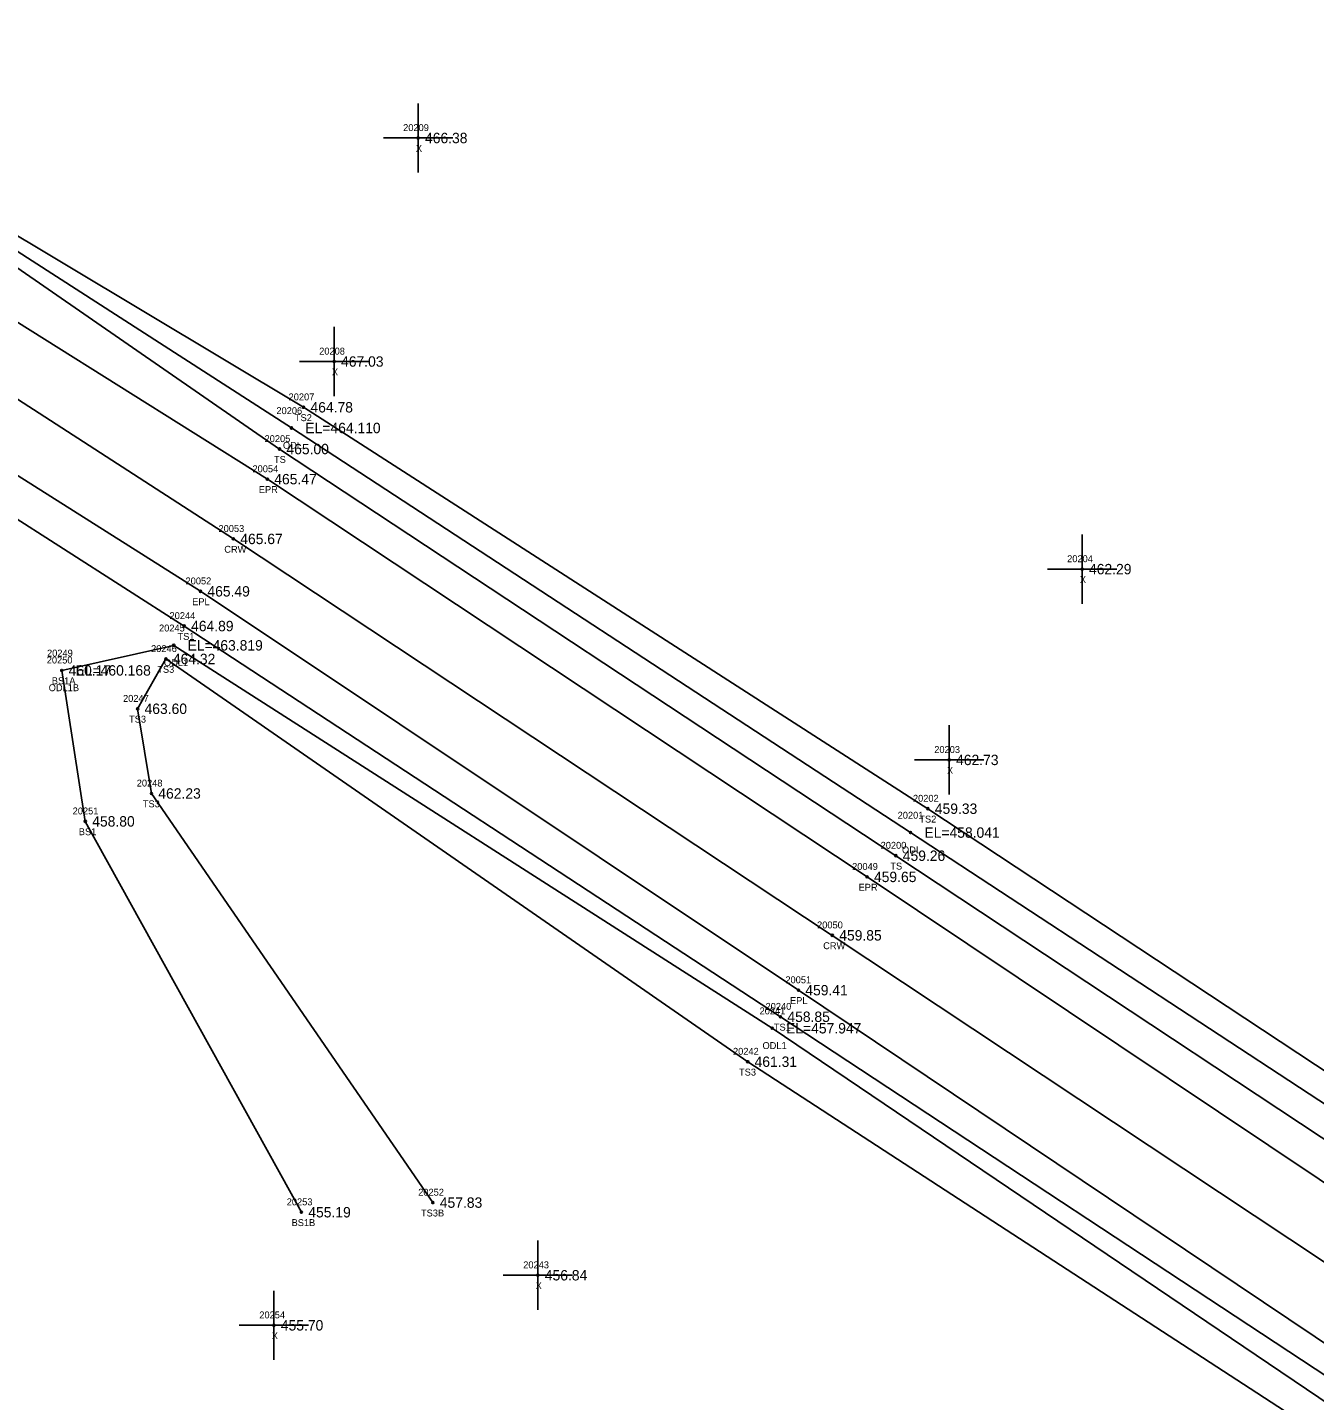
# Model space of a CAD drawing. Extents: x 1797709 to 1799052, y 896018 to 896955.
# Drawn here: x 1797809.4 to 1797995.4, y 896720 to 896918.3 of the extents above; entities that cross this region are included whole.
import ezdxf

# ---------------------------------------------------------------- set-up
doc = ezdxf.new("R2010")
doc.units = 0
for name, color, linetype in [('RD_DTM_BkLn1', 7, 'Continuous'), ('RD_DTM_BkLn2', 7, 'Continuous'), ('RD_DTM_BkLn_txCode', 7, 'Continuous'), ('RD_EX_H2O', 7, 'Continuous'), ('RD_EX_H2O_txCode', 7, 'Continuous'), ('RD_EX_Misc', 7, 'Continuous'), ('RD_EX_Misc_txCode', 7, 'Continuous'), ('RD_EX_Road', 7, 'Continuous'), ('RD_EX_Road_txCode', 7, 'Continuous'), ('RD_EX_TX_H2O_ELEV', 7, 'Continuous'), ('RD_EX_TX_Misc_ELEV', 7, 'Continuous'), ('RD_EX_TX_Road_ELEV', 7, 'Continuous'), ('RD_HC_Survey_ELEV', 7, 'Continuous'), ('RD_HC_Survey_txCode', 7, 'Continuous'), ('RD_SMD_Locator', 7, 'Continuous')]:
    doc.layers.add(name, color=color, linetype=linetype)

msp = doc.modelspace()

# ---------------------------------------------------------------- linework, layer by layer
at = {"layer": 'RD_DTM_BkLn1'}
msp.add_lwpolyline([(1798362.28, 896497.65), (1798275.53, 896555.51), (1798188.06, 896613.78), (1798100.6, 896671.09), (1798012.14, 896729.83), (1797925.7, 896787.19), (1797839.16, 896844.44), (1797754.21, 896899.34)], dxfattribs=at)
at = {"layer": 'RD_DTM_BkLn2'}
for points in [[(1798369.83, 896508.31), (1798367.91, 896513.92), (1798355.6, 896518.28), (1798283.49, 896566.57), (1798194.13, 896625.72), (1798108.66, 896683.13), (1798020.94, 896741.77), (1797934.88, 896798.69), (1797845.83, 896857.42), (1797757.7, 896918.3)], [(1798314.49, 896563.64), (1798288.01, 896573.8), (1798198.07, 896632.21), (1798113.28, 896689.71), (1798026.02, 896748.38), (1797939.51, 896805.48), (1797849.3, 896863.45), (1797757.7, 896918.3)], [(1798355.54, 896486.7), (1798350.74, 896485.38), (1798342.98, 896495.49), (1798267.09, 896545.1), (1798179.21, 896602.99), (1798092.54, 896661.13), (1798003.24, 896719.48), (1797918.21, 896775.43), (1797832.05, 896831.86), (1797744.82, 896887.66)], [(1798197.99, 896581.94), (1798175.06, 896597.9), (1798088.07, 896654.61), (1797998.87, 896713.42), (1797913.47, 896768.94), (1797829.42, 896827.1), (1797825.33, 896819.91), (1797827.32, 896807.68), (1797867.99, 896748.59)], [(1797814.36, 896825.45), (1797817.77, 896803.65), (1797848.99, 896747.2)]]:
    msp.add_lwpolyline(points, dxfattribs=at)
at = {"layer": 'RD_EX_H2O'}
for points in [[(1798314.49, 896563.64), (1798286.18, 896571.49), (1798196.7, 896629.98), (1798111.06, 896686.41), (1798023.38, 896745.41), (1797937.01, 896802.03), (1797847.56, 896860.46), (1797757.7, 896918.3)], [(1798197.99, 896581.94), (1798176.34, 896599.45), (1798090.08, 896657.76), (1798001.35, 896716.83), (1797917.02, 896773.77), (1797830.54, 896829.07), (1797814.36, 896825.45)]]:
    msp.add_lwpolyline(points, dxfattribs=at)
at = {"layer": 'RD_EX_Misc'}
for p, q in [((1797865.85, 896897.34), (1797865.85, 896907.34)), ((1797860.85, 896902.34), (1797870.85, 896902.34)), ((1797853.72, 896865.06), (1797853.72, 896875.06)), ((1797848.72, 896870.06), (1797858.72, 896870.06)), ((1797961.79, 896835.08), (1797961.79, 896845.08)), ((1797956.79, 896840.08), (1797966.79, 896840.08)), ((1797942.58, 896807.52), (1797942.58, 896817.52)), ((1797937.58, 896812.52), (1797947.58, 896812.52)), ((1797883.16, 896733.1), (1797883.16, 896743.1)), ((1797878.16, 896738.1), (1797888.16, 896738.1)), ((1797845.02, 896725.87), (1797845.02, 896735.87)), ((1797840.02, 896730.87), (1797850.02, 896730.87))]:
    msp.add_line(p, q, dxfattribs=at)
at = {"layer": 'RD_EX_Road'}
for points in [[(1798362.28, 896497.65), (1798367.54, 896505.07), (1798280.71, 896562.69), (1798193.2, 896621.02), (1798104.98, 896679.23), (1798017.88, 896737.39), (1797930.72, 896795.63), (1797844.07, 896853.07), (1797758.11, 896906.97)], [(1798362.28, 896497.65), (1798357.85, 896490.18), (1798271.29, 896548.71), (1798183.2, 896606.17), (1798096.06, 896663.44), (1798006.57, 896721.75), (1797920.8, 896779.27), (1797834.41, 896836.87), (1797748.77, 896891.01)]]:
    msp.add_lwpolyline(points, dxfattribs=at)
at = {"layer": 'RD_SMD_Locator'}
for centre in [(1797865.85, 896902.34), (1797853.72, 896870.06), (1797849.3, 896863.45), (1797847.56, 896860.46), (1797845.83, 896857.42), (1797844.07, 896853.07), (1797839.16, 896844.44), (1797961.79, 896840.08), (1797834.41, 896836.87), (1797832.05, 896831.86), (1797830.54, 896829.07), (1797829.42, 896827.1), (1797814.36, 896825.45), (1797814.36, 896825.45), (1797825.33, 896819.91), (1797942.58, 896812.52), (1797827.32, 896807.68), (1797939.51, 896805.48), (1797817.77, 896803.65), (1797937.01, 896802.03), (1797934.88, 896798.69), (1797930.72, 896795.63), (1797925.7, 896787.19), (1797920.8, 896779.27), (1797918.21, 896775.43), (1797917.02, 896773.77), (1797913.47, 896768.94), (1797867.99, 896748.59), (1797848.99, 896747.2), (1797883.16, 896738.1), (1797845.02, 896730.87)]:
    msp.add_circle(centre, 0.15, dxfattribs=at)

# ---------------------------------------------------------------- texts
at = {"layer": 'RD_DTM_BkLn_txCode'}
for s, p in [('20207', (1797847.14, 896864.45)), ('TS2', (1797848.05, 896861.45)), ('20205', (1797843.67, 896858.42)), ('TS', (1797845.03, 896855.42)), ('20244', (1797829.94, 896832.86)), ('20246', (1797827.27, 896828.1)), ('TS1', (1797831.09, 896829.86)), ('20250', (1797812.2, 896826.45)), ('TS3', (1797828.17, 896825.1)), ('BS1A', (1797812.93, 896823.45)), ('20247', (1797823.22, 896820.91)), ('TS3', (1797824.09, 896817.91)), ('20248', (1797825.2, 896808.68)), ('20202', (1797937.35, 896806.48)), ('20251', (1797815.94, 896804.65)), ('TS3', (1797826.08, 896805.68)), ('TS2', (1797938.27, 896803.48)), ('BS1', (1797816.83, 896801.65)), ('20200', (1797932.68, 896799.69)), ('TS', (1797934.08, 896796.69)), ('20240', (1797916.05, 896776.43)), ('TS1', (1797917.25, 896773.43)), ('20242', (1797911.35, 896769.94)), ('TS3', (1797912.22, 896766.94)), ('20252', (1797865.87, 896749.59)), ('20253', (1797846.87, 896748.2)), ('TS3B', (1797866.27, 896746.59)), ('BS1B', (1797847.57, 896745.2))]:
    msp.add_text(s, height=1, dxfattribs=at).set_placement(p)
at = {"layer": 'RD_EX_H2O_txCode'}
for s, p in [('20206', (1797845.38, 896862.46)), ('ODL', (1797846.32, 896857.46)), ('20245', (1797828.42, 896831.07)), ('20249', (1797812.24, 896827.45)), ('ODL1', (1797829.13, 896826.07)), ('ODL1B', (1797812.48, 896822.45)), ('20201', (1797935.14, 896804.03)), ('ODL', (1797935.77, 896799.03)), ('20241', (1797915.19, 896775.77)), ('ODL1', (1797915.61, 896770.77))]:
    msp.add_text(s, height=1, dxfattribs=at).set_placement(p)
at = {"layer": 'RD_EX_Misc_txCode'}
for s, p in [('20209', (1797863.69, 896903.34)), ('X', (1797865.53, 896900.34)), ('20208', (1797851.56, 896871.06)), ('X', (1797853.4, 896868.06)), ('20204', (1797959.63, 896841.08)), ('X', (1797961.47, 896838.08)), ('20203', (1797940.43, 896813.52)), ('X', (1797942.27, 896810.52)), ('20243', (1797881.04, 896739.1)), ('X', (1797882.84, 896736.1)), ('20254', (1797842.91, 896731.87)), ('X', (1797844.71, 896728.87))]:
    msp.add_text(s, height=1, dxfattribs=at).set_placement(p)
at = {"layer": 'RD_EX_Road_txCode'}
for s, p in [('20054', (1797841.92, 896854.07)), ('EPR', (1797842.84, 896851.07)), ('20052', (1797832.25, 896837.87)), ('EPL', (1797833.21, 896834.87)), ('20049', (1797928.56, 896796.63)), ('EPR', (1797929.49, 896793.63)), ('20051', (1797918.92, 896780.27)), ('EPL', (1797919.59, 896777.27))]:
    msp.add_text(s, height=1, dxfattribs=at).set_placement(p)
at = {"layer": 'RD_EX_TX_H2O_ELEV'}
for s, p in [('EL=464.110', (1797849.56, 896859.71)), ('EL=463.819', (1797832.54, 896828.32)), ('EL=460.168', (1797816.36, 896824.7)), ('EL=458.041', (1797939.01, 896801.28)), ('EL=457.947', (1797919.02, 896773.02))]:
    msp.add_text(s, height=1.5, dxfattribs=at).set_placement(p)
at = {"layer": 'RD_EX_TX_Misc_ELEV'}
for s, p in [('466.38', (1797866.85, 896901.59)), ('467.03', (1797854.72, 896869.31)), ('464.78', (1797850.3, 896862.7)), ('465.00', (1797846.83, 896856.67)), ('462.29', (1797962.79, 896839.33)), ('464.89', (1797833.05, 896831.11)), ('464.32', (1797830.42, 896826.35)), ('460.17', (1797815.36, 896824.7)), ('463.60', (1797826.33, 896819.16)), ('462.73', (1797943.58, 896811.77)), ('462.23', (1797828.32, 896806.93)), ('459.33', (1797940.51, 896804.73)), ('458.80', (1797818.77, 896802.9)), ('459.26', (1797935.88, 896797.94)), ('458.85', (1797919.21, 896774.68)), ('461.31', (1797914.47, 896768.19)), ('455.19', (1797849.99, 896746.45)), ('457.83', (1797868.99, 896747.84)), ('456.84', (1797884.16, 896737.35)), ('455.70', (1797846.02, 896730.12))]:
    msp.add_text(s, height=1.5, dxfattribs=at).set_placement(p)
at = {"layer": 'RD_EX_TX_Road_ELEV'}
for s, p in [('465.47', (1797845.07, 896852.32)), ('465.49', (1797835.41, 896836.12)), ('459.65', (1797931.72, 896794.88)), ('459.41', (1797921.8, 896778.52))]:
    msp.add_text(s, height=1.5, dxfattribs=at).set_placement(p)
at = {"layer": 'RD_HC_Survey_ELEV'}
for s, p in [('465.67', (1797840.16, 896843.69)), ('459.85', (1797926.7, 896786.44))]:
    msp.add_text(s, height=1.5, dxfattribs=at).set_placement(p)
at = {"layer": 'RD_HC_Survey_txCode'}
for s, p in [('20053', (1797837.01, 896845.44)), ('CRW', (1797837.85, 896842.44)), ('20050', (1797923.5, 896788.19)), ('CRW', (1797924.38, 896785.19))]:
    msp.add_text(s, height=1, dxfattribs=at).set_placement(p)

doc.saveas('drawing.dxf')
